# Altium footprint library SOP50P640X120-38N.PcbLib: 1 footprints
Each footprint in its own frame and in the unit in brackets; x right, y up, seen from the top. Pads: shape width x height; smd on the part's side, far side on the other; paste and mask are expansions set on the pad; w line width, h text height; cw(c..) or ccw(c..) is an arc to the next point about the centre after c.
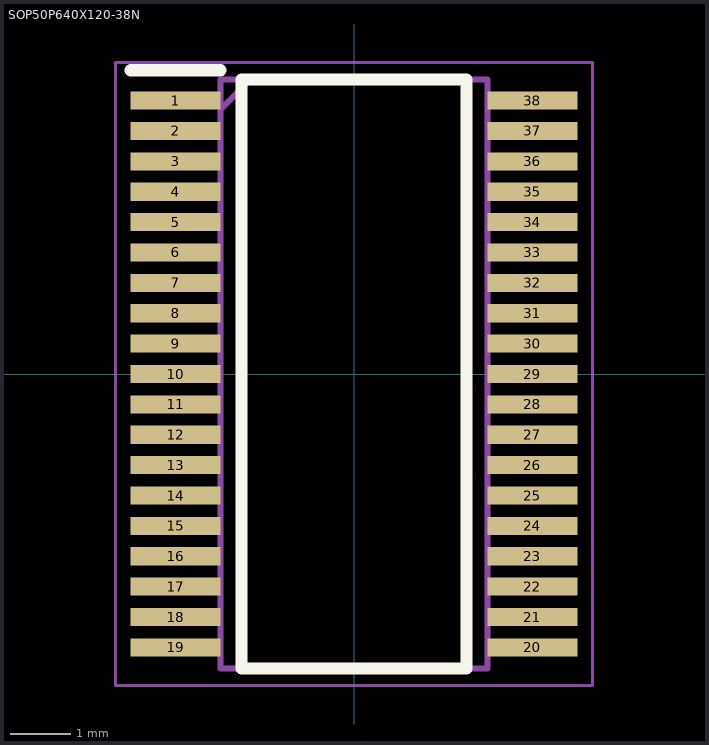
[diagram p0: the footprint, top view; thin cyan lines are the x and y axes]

## SOP50P640X120-38N [mm]
pads (38):
  rect 1.475x0.3 smd: 1(-2.938,4.5) 2(-2.938,4) 3(-2.938,3.5) 4(-2.938,3) 5(-2.938,2.5) 6(-2.938,2) 7(-2.938,1.5) 8(-2.938,1) 9(-2.938,0.5) 10(-2.938,0) 11(-2.938,-0.5) 12(-2.938,-1) 13(-2.938,-1.5) 14(-2.938,-2) 15(-2.938,-2.5) 16(-2.938,-3) 17(-2.938,-3.5) 18(-2.938,-4) 19(-2.938,-4.5) 20(2.938,-4.5) 21(2.938,-4) 22(2.938,-3.5) 23(2.938,-3) 24(2.938,-2.5) 25(2.938,-2) 26(2.938,-1.5) 27(2.938,-1) 28(2.938,-0.5) 29(2.938,0) 30(2.938,0.5) 31(2.938,1) 32(2.938,1.5) 33(2.938,2) 34(2.938,2.5) 35(2.938,3) 36(2.938,3.5) 37(2.938,4) 38(2.938,4.5)
Top Overlay:
  lines w0.2: -3.675,5 -2.2,5 ; -1.85,-4.85 1.85,-4.85 1.85,4.85 -1.85,4.85 -1.85,-4.85
Mechanical 15:
  lines w0.1: -2.2,4.35 -1.7,4.85 ; -2.2,-4.85 2.2,-4.85 2.2,4.85 -2.2,4.85 -2.2,-4.85
Mechanical 20:
  lines w0.05: -3.925,-5.125 3.925,-5.125 3.925,5.125 -3.925,5.125 -3.925,-5.125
